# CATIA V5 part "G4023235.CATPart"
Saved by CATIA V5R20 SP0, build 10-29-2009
Part number: G4023235
Revision: 11
Definition: design
Nomenclature: G4023235
Source: made
Description: NOT SPECIFIED
Bounding box of the stored display mesh (mm): x -20 to 35, y -22.5 to 22.5, z -22.5 to 22.5
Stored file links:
  C:\Users\Raffaele\Desktop\3D X SITO CF\BOLEX\26-BUSH REF 402\G4023235.CATPart
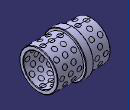
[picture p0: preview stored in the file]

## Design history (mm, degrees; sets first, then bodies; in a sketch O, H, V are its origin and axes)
Body1 "MANIFOLD_SOLID_BREP #9701" (main body)
  Solid1: solid without history
Body2 "MANIFOLD_SOLID_BREP #9856"
  Solid2: solid without history
Body3 "MANIFOLD_SOLID_BREP #10011"
  Solid3: solid without history
Body4 "MANIFOLD_SOLID_BREP #10164"
  Solid4: solid without history
Body5 "MANIFOLD_SOLID_BREP #10321"
  Solid5: solid without history
Body6 "MANIFOLD_SOLID_BREP #10474"
  Solid6: solid without history
Body7 "MANIFOLD_SOLID_BREP #10627"
  Solid7: solid without history
Body8 "MANIFOLD_SOLID_BREP #10784"
  Solid8: solid without history
Body9 "MANIFOLD_SOLID_BREP #10937"
  Solid9: solid without history
Body10 "MANIFOLD_SOLID_BREP #11094"
  Solid10: solid without history
Body11 "MANIFOLD_SOLID_BREP #11251"
  Solid11: solid without history
Body12 "MANIFOLD_SOLID_BREP #11408"
  Solid12: solid without history
Body13 "MANIFOLD_SOLID_BREP #11565"
  Solid13: solid without history
Body14 "MANIFOLD_SOLID_BREP #11722"
  Solid14: solid without history
Body15 "MANIFOLD_SOLID_BREP #11879"
  Solid15: solid without history
Body16 "MANIFOLD_SOLID_BREP #12036"
  Solid16: solid without history
Body17 "MANIFOLD_SOLID_BREP #12193"
  Solid17: solid without history
Body18 "MANIFOLD_SOLID_BREP #12346"
  Solid18: solid without history
Body19 "MANIFOLD_SOLID_BREP #12503"
  Solid19: solid without history
Body20 "MANIFOLD_SOLID_BREP #12656"
  Solid20: solid without history
Body21 "MANIFOLD_SOLID_BREP #12809"
  Solid21: solid without history
Body22 "MANIFOLD_SOLID_BREP #12966"
  Solid22: solid without history
Body23 "MANIFOLD_SOLID_BREP #13119"
  Solid23: solid without history
Body24 "MANIFOLD_SOLID_BREP #13274"
  Solid24: solid without history
Body25 "MANIFOLD_SOLID_BREP #13429"
  Solid25: solid without history
Body26 "MANIFOLD_SOLID_BREP #13582"
  Solid26: solid without history
Body27 "MANIFOLD_SOLID_BREP #13739"
  Solid27: solid without history
Body28 "MANIFOLD_SOLID_BREP #13892"
  Solid28: solid without history
Body29 "MANIFOLD_SOLID_BREP #14045"
  Solid29: solid without history
Body30 "MANIFOLD_SOLID_BREP #14202"
  Solid30: solid without history
Body31 "MANIFOLD_SOLID_BREP #14355"
  Solid31: solid without history
Body32 "MANIFOLD_SOLID_BREP #14510"
  Solid32: solid without history
Body33 "MANIFOLD_SOLID_BREP #14665"
  Solid33: solid without history
Body34 "MANIFOLD_SOLID_BREP #14822"
  Solid34: solid without history
Body35 "MANIFOLD_SOLID_BREP #14979"
  Solid35: solid without history
Body36 "MANIFOLD_SOLID_BREP #15136"
  Solid36: solid without history
Body37 "MANIFOLD_SOLID_BREP #15293"
  Solid37: solid without history
Body38 "MANIFOLD_SOLID_BREP #15450"
  Solid38: solid without history
Body39 "MANIFOLD_SOLID_BREP #15607"
  Solid39: solid without history
Body40 "MANIFOLD_SOLID_BREP #15764"
  Solid40: solid without history
Body41 "MANIFOLD_SOLID_BREP #15921"
  Solid41: solid without history
Body42 "MANIFOLD_SOLID_BREP #16074"
  Solid42: solid without history
Body43 "MANIFOLD_SOLID_BREP #16227"
  Solid43: solid without history
Body44 "MANIFOLD_SOLID_BREP #16384"
  Solid44: solid without history
Body45 "MANIFOLD_SOLID_BREP #16541"
  Solid45: solid without history
Body46 "MANIFOLD_SOLID_BREP #16694"
  Solid46: solid without history
Body47 "MANIFOLD_SOLID_BREP #16847"
  Solid47: solid without history
Body48 "MANIFOLD_SOLID_BREP #17000"
  Solid48: solid without history
Body49 "MANIFOLD_SOLID_BREP #17153"
  Solid49: solid without history
Body50 "MANIFOLD_SOLID_BREP #17310"
  Solid50: solid without history
Body51 "MANIFOLD_SOLID_BREP #17467"
  Solid51: solid without history
Body52 "MANIFOLD_SOLID_BREP #17620"
  Solid52: solid without history
Body53 "MANIFOLD_SOLID_BREP #17773"
  Solid53: solid without history
Body54 "MANIFOLD_SOLID_BREP #17928"
  Solid54: solid without history
Body55 "MANIFOLD_SOLID_BREP #18083"
  Solid55: solid without history
Body56 "MANIFOLD_SOLID_BREP #18238"
  Solid56: solid without history
Body57 "MANIFOLD_SOLID_BREP #18393"
  Solid57: solid without history
Body58 "MANIFOLD_SOLID_BREP #18550"
  Solid58: solid without history
Body59 "MANIFOLD_SOLID_BREP #18707"
  Solid59: solid without history
Body60 "MANIFOLD_SOLID_BREP #18864"
  Solid60: solid without history
Body61 "MANIFOLD_SOLID_BREP #19021"
  Solid61: solid without history
Body62 "MANIFOLD_SOLID_BREP #19178"
  Solid62: solid without history
Body63 "MANIFOLD_SOLID_BREP #19335"
  Solid63: solid without history
Body64 "MANIFOLD_SOLID_BREP #19492"
  Solid64: solid without history
Body65 "MANIFOLD_SOLID_BREP #19649"
  Solid65: solid without history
